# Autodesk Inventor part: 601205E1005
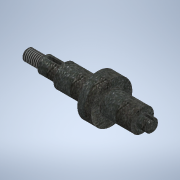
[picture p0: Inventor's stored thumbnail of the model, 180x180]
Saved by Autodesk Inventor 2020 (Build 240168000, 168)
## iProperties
Created: 2020-12
Part Number: 601205E1005
Material: 강철
Document SubType Name: Modeling
Designer: USER
Density: 7.85 g/cm^3
Appearance: 플레이트
Mass: 270.215 g
Surface Area: 85.0141 cm^2
Volume: 34.4223 cm^3
Author: USER
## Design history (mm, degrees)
sketch "스케치1"
  geometry: L1 (-55, 0)-(55, 0); L2 (-55, 0)-(-55, 5); L3 (-55, 5)-(-40, 5); L4 (-40, 5)-(-40, 7); L5 (-40, 7)-(-22, 7); L6 (-22, 7)-(-22, 10); L7 (-22, 10)-(7, 10); L8 (7, 10)-(7, 18); L9 (7, 18)-(19, 18); L10 (19, 18)-(19, 10); L11 (19, 10)-(46, 10); L12 (46, 10)-(46, 5.5); L13 (46, 5.5)-(55, 5.5); L14 (55, 5.5)-(55, 0); 2 further points
  constraints: 28 end point, 11 perpendicular, 2 point on line, 1 coincident, 1 horizontal, 1 midpoint, 1 vertical
  dimensions: "d0" = 110 distance of L1.start L1.end; "d1" = 10 diameter of L3 L1; "d2" = 15 distance of L2.end L3.end; "d3" = 18 distance of L4.end L5.end; "d4" = 14 diameter of L5 L1; "d5" = 20 diameter of L7 L1; "d6" = 36 diameter of L9 L1; "d7" = 12 distance of L8.end L9.end; "d8" = 29 distance of L6.end L7.end; "d9" = 27 distance of L10.end L11.end; "d11" = 11 diameter of L13 L1
revolve "회전1" sketch "스케치1" stored, may be unused: angle "d12" = 90 deg
chamfer "모따기1" distance "d13" = 1; stored, may be unused: second distance "d14" = 2, angle "d15" = 30 deg
fillet "모깎기1" dims "d16" = 0.6
node "작업 평면1"
sketch "스케치2"
  geometry: L1 (-9, 7)-(-9, -7) reference; L2 (8, -7)-(8, 7) reference; L3 (8, 0)-(6, 0); L4 (6, 0)-(-6, 0); L5 (-6, 1.5)-(-6, -1.5); L6 (-6, -1.5)-(6, -1.5); L7 (6, -1.5)-(6, 1.5); L8 (6, 1.5)-(-6, 1.5); 1 further point
  constraints: 12 end point, 2 horizontal, 2 midpoint, 1 perpendicular, 1 point on line, 1 vertical
  dimensions: "d17" = 2 distance of L3.start L3.end; "d18" = 12 distance of L4.end L3.end; "d19" = 3 distance of L5.start L5.end; "d20" = 12 distance of L5.end L6.end; "d21" = 3 distance of L6.end L7.end
extrude "돌출1" cut sketch "스케치2" distance "d22" = 3; taper "d23" = 0 deg
fillet "모깎기2" dims "d24" = 1.5
node "작업 평면2"
sketch "스케치3"
  geometry: L1 (4.5, 5.5)-(4.5, -5.5) reference; L2 (-3.5, 5.5)-(-3.5, -5.5) reference; L3 (4.5, 10)-(4.5, -10) reference; L4 (4.5, 0)-(3.5, 0); L5 (3.5, 1.25)-(3.5, -1.25); L6 (3.5, -1.25)-(-6.5, -1.25); L7 (3.5, 1.25)-(-6.5, 1.25); L8 (-6.5, -1.25)-(-6.5, 1.25); 1 further point
  constraints: 10 end point, 3 horizontal, 2 midpoint, 1 vertical
  dimensions: "d25" = 1 distance of L4.end L4.start; "d26" = 2.5 distance of L5.start L5.end; "d28" = 10 distance of L5.start L7.end; "d29" = 10 distance of L5.end L6.end
extrude "돌출2" cut sketch "스케치3" distance "d30" = 2.5; taper "d31" = 0 deg
feature "스레드1" dims "d32" = 14, "d33" = 0
node "솔리드1"
node "투영된 루프1"
node "투영된 루프2"
